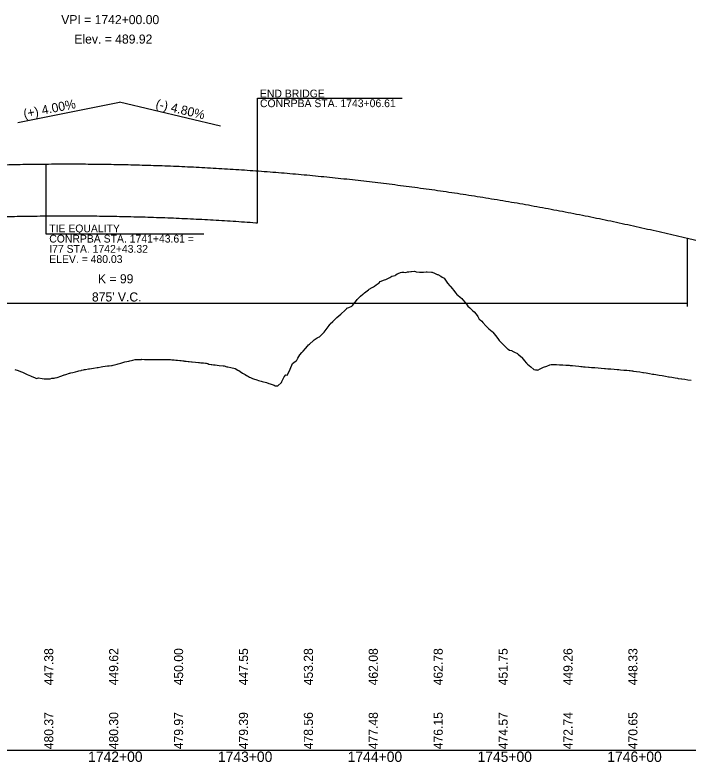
# Model space of a CAD drawing. Extents: x 2017200 to 2047700, y 854850 to 893350.
# Drawn here: x 2022119 to 2022638, y 874091 to 874667 of the extents above; entities that cross this region are included whole.
import ezdxf

# ---------------------------------------------------------------- set-up
doc = ezdxf.new("R2010")
doc.units = 0
for name, color, linetype in [('RD_DDB_GradeTX', 7, 'Continuous'), ('RD_DDB_Profile_EX', 7, 'Continuous'), ('RD_DDB_Profile_Lbl', 7, 'Continuous'), ('RD_DDB_Profile_PR', 7, 'Continuous'), ('RD_DDB_StaTX', 7, 'Continuous'), ('RD_DDB_StripGrade', 7, 'Continuous'), ('RD_DDB_VCLbl', 7, 'Continuous'), ('RD_GPK_Profile_Cell', 7, 'Continuous'), ('RD_PD_Bridge', 7, 'Continuous')]:
    doc.layers.add(name, color=color, linetype=linetype)

msp = doc.modelspace()

# ---------------------------------------------------------------- linework, layer by layer
at = {"layer": 'RD_DDB_GradeTX'}
for p in [(2022121.55, 874583.91), (2022277.79, 874580.93)]:
    msp.add_line(p, (2022200, 874599.6), dxfattribs=at)
at = {"layer": 'RD_DDB_Profile_EX'}
msp.add_lwpolyline([(2022119.33, 874393.34), (2022121.82, 874392.73), (2022122.35, 874392.5), (2022124.57, 874391.55), (2022125.38, 874391.29), (2022126.82, 874390.58), (2022128.41, 874389.89), (2022128.94, 874389.65), (2022130.12, 874388.99), (2022131.43, 874388.47), (2022132.52, 874388.04), (2022134.46, 874387.18), (2022135.63, 874386.67), (2022136.1, 874386.43), (2022137.66, 874386.99), (2022140.51, 874386.48), (2022141.88, 874386.23), (2022142.56, 874386.2), (2022143.5, 874386.17), (2022145.73, 874386.14), (2022146.56, 874386.37), (2022147.87, 874386.73), (2022149.59, 874386.85), (2022150.49, 874386.91), (2022151.92, 874387.4), (2022152.62, 874387.62), (2022154.11, 874388.07), (2022155.64, 874388.63), (2022157.28, 874389.22), (2022157.74, 874389.4), (2022158.7, 874389.7), (2022161.37, 874390.55), (2022161.7, 874390.64), (2022162.6, 874390.87), (2022164.03, 874391.23), (2022165.01, 874391.5), (2022166.18, 874391.76), (2022167.88, 874392.21), (2022168.66, 874392.4), (2022170.43, 874392.79), (2022170.78, 874392.86), (2022172.32, 874393.19), (2022173.13, 874393.36), (2022173.8, 874393.5), (2022175.98, 874393.95), (2022176.83, 874394.06), (2022178.34, 874394.25), (2022179.85, 874394.47), (2022182.88, 874394.94), (2022183.52, 874395.05), (2022185.91, 874395.45), (2022187.03, 874395.64), (2022188.93, 874395.92), (2022190.73, 874396.17), (2022191.96, 874396.33), (2022193.79, 874396.56), (2022194.43, 874396.64), (2022194.99, 874396.76), (2022196.18, 874397.03), (2022198.15, 874397.5), (2022198.87, 874397.73), (2022201.04, 874398.4), (2022201.88, 874398.65), (2022204.07, 874399.24), (2022205.61, 874399.68), (2022207.09, 874399.99), (2022208.01, 874400.18), (2022209.15, 874400.38), (2022210.38, 874400.69), (2022212.02, 874401.05), (2022213.14, 874401.1), (2022216.17, 874401.25), (2022216.95, 874401.27), (2022217.31, 874401.29), (2022219.21, 874401.27), (2022221.26, 874401.26), (2022221.73, 874401.25), (2022222.22, 874401.25), (2022223.51, 874401.23), (2022224.26, 874401.21), (2022225.25, 874401.21), (2022225.76, 874401.2), (2022226.77, 874401.21), (2022228.28, 874401.21), (2022229.28, 874401.19), (2022230.25, 874401.18), (2022231.3, 874401.17), (2022231.78, 874401.17), (2022232.49, 874401.16), (2022234.33, 874401.15), (2022234.73, 874401.15), (2022236.96, 874401.15), (2022237.36, 874401.15), (2022238.62, 874401.13), (2022239.34, 874401.05), (2022240.38, 874400.95), (2022241.66, 874400.82), (2022242.03, 874400.78), (2022243.41, 874400.65), (2022244.05, 874400.59), (2022244.71, 874400.52), (2022246.44, 874400.36), (2022247.39, 874400.26), (2022248.83, 874400.09), (2022249.46, 874400.03), (2022250.06, 874399.98), (2022251.22, 874399.89), (2022252.76, 874399.73), (2022253.62, 874399.65), (2022255.51, 874399.45), (2022255.99, 874399.4), (2022258.54, 874399.14), (2022260.84, 874398.93), (2022261.57, 874398.84), (2022262.75, 874398.7), (2022263.47, 874398.62), (2022264.76, 874398.48), (2022266.22, 874398.29), (2022266.74, 874398.23), (2022267.62, 874398.12), (2022268.15, 874398.05), (2022268.79, 874397.57), (2022270.65, 874397.34), (2022271.06, 874397.28), (2022272.51, 874397.08), (2022273.67, 874396.92), (2022276.7, 874396.58), (2022279.73, 874396.24), (2022280.56, 874396.14), (2022281.45, 874395.93), (2022282.01, 874395.74), (2022282.75, 874395.58), (2022283.41, 874395.44), (2022285.78, 874394.95), (2022288.97, 874394.29), (2022291.15, 874393.04), (2022291.83, 874392.62), (2022292.94, 874391.95), (2022294.86, 874390.73), (2022295.72, 874390.19), (2022296.92, 874389.46), (2022297.88, 874388.91), (2022298.63, 874388.48), (2022300.24, 874387.59), (2022300.91, 874387.21), (2022302.38, 874386.38), (2022303.94, 874386.01), (2022304.92, 874385.77), (2022305.88, 874385.44), (2022306.96, 874385.08), (2022309.13, 874384.36), (2022309.99, 874384.16), (2022313.12, 874383.42), (2022314.96, 874382.75), (2022316.04, 874382.35), (2022317.65, 874381.76), (2022318.26, 874381.55), (2022319.07, 874381.26), (2022319.92, 874380.93), (2022321.31, 874380.87), (2022321.88, 874380.84), (2022324.8, 874383.5), (2022325.12, 874384.16), (2022326.88, 874387.8), (2022328.15, 874389.25), (2022329.22, 874389.1), (2022331.17, 874392.81), (2022331.58, 874393.57), (2022333.32, 874398.15), (2022334.2, 874398.78), (2022335.97, 874400.04), (2022336.72, 874400.63), (2022337.43, 874402.12), (2022338.85, 874404.71), (2022340.35, 874406.53), (2022341.56, 874407.51), (2022343.28, 874409.66), (2022344.71, 874411.44), (2022345.69, 874412.51), (2022346.31, 874413.03), (2022349.33, 874415.69), (2022349.85, 874416.32), (2022352.36, 874417.84), (2022353.38, 874418.45), (2022354.02, 874418.56), (2022355.38, 874419.97), (2022357.69, 874422.31), (2022358.41, 874423.27), (2022361.44, 874427.39), (2022361.98, 874428.13), (2022362.39, 874428.73), (2022364.46, 874430.45), (2022366.26, 874432.33), (2022366.61, 874432.72), (2022367.49, 874433.5), (2022370.52, 874436.16), (2022370.83, 874436.32), (2022373.54, 874439.04), (2022374.77, 874440.27), (2022375.08, 874440.6), (2022376.57, 874441.23), (2022379, 874442.24), (2022379.6, 874442.79), (2022382.62, 874446.71), (2022383.21, 874447.47), (2022383.61, 874447.91), (2022385.65, 874449.84), (2022387.41, 874451.5), (2022387.9, 874451.84), (2022388.68, 874452.47), (2022391.7, 874454.9), (2022392.21, 874455.3), (2022394.73, 874456.61), (2022395.76, 874457.14), (2022396.53, 874457.59), (2022397.75, 874458.57), (2022399.92, 874460.3), (2022400.88, 874461.32), (2022404.06, 874462.53), (2022405.24, 874462.71), (2022406.83, 874463.6), (2022408.18, 874464.35), (2022409.86, 874465.34), (2022412.3, 874465.97), (2022412.89, 874466.38), (2022414.01, 874467.16), (2022415.91, 874467.95), (2022416.39, 874468.15), (2022417.37, 874468.47), (2022418.42, 874468.41), (2022418.94, 874468.37), (2022420.48, 874468.27), (2022421.97, 874468.62), (2022422.85, 874468.82), (2022424.55, 874469.07), (2022424.99, 874469.08), (2022427.3, 874469.14), (2022428.02, 874468.97), (2022428.61, 874468.84), (2022431.04, 874468.57), (2022431.77, 874468.49), (2022432.65, 874468.41), (2022434.07, 874468.55), (2022436.26, 874468.76), (2022436.69, 874468.72), (2022437.1, 874468.7), (2022440.24, 874468.58), (2022440.77, 874468.53), (2022442.6, 874467.67), (2022444.71, 874466.67), (2022445.3, 874466.54), (2022447.54, 874465.33), (2022448.69, 874464.71), (2022450.01, 874463.87), (2022452.66, 874460.06), (2022454.46, 874458.02), (2022454.96, 874457.46), (2022456.61, 874455.56), (2022457.43, 874454.51), (2022459.09, 874452.38), (2022459.9, 874451.2), (2022460.54, 874450.76), (2022462.37, 874449.26), (2022463.76, 874448.14), (2022464.46, 874447.24), (2022464.84, 874446.77), (2022467.32, 874443.73), (2022467.9, 874443.03), (2022468.45, 874442.36), (2022469.79, 874441.08), (2022472.26, 874438.72), (2022473.19, 874437.91), (2022474.73, 874436), (2022476.1, 874434.31), (2022477.2, 874432.23), (2022477.96, 874431.59), (2022479.07, 874430.71), (2022479.96, 874429.75), (2022482.15, 874427.22), (2022482.76, 874426.52), (2022483.79, 874425.53), (2022484.62, 874424.8), (2022487.09, 874422.64), (2022487.62, 874422.18), (2022489.56, 874419.66), (2022491.41, 874417.28), (2022492.04, 874416.44), (2022492.49, 874415.83), (2022494.51, 874413.68), (2022495.2, 874412.94), (2022496.98, 874411.28), (2022497.42, 874410.88), (2022498.98, 874409.4), (2022499.45, 874409.09), (2022500.45, 874408.45), (2022501.92, 874408.01), (2022502.38, 874407.88), (2022502.82, 874407.67), (2022503.82, 874407.12), (2022504.4, 874406.81), (2022506.49, 874405.68), (2022506.87, 874405.38), (2022507.39, 874404.97), (2022509.34, 874403.18), (2022509.73, 874402.82), (2022511.22, 874401.26), (2022511.81, 874400.5), (2022513.55, 874398.29), (2022514.28, 874397.64), (2022516.76, 874395.49), (2022519.16, 874393.42), (2022520.37, 874393.27), (2022521.7, 874393.1), (2022522.24, 874393.03), (2022524.17, 874393.94), (2022526.71, 874395.11), (2022529.12, 874396.08), (2022531.59, 874397.06), (2022532.53, 874397.42), (2022534.06, 874397.34), (2022536.53, 874397.2), (2022539, 874397.07), (2022539.55, 874397.03), (2022541.48, 874396.94), (2022543.95, 874396.82), (2022545.62, 874396.74), (2022546.42, 874396.66), (2022547.06, 874396.59), (2022548.89, 874396.41), (2022551.37, 874396.17), (2022553.84, 874395.92), (2022555.3, 874395.78), (2022556.31, 874395.71), (2022557.52, 874395.62), (2022558.78, 874395.5), (2022561.25, 874395.24), (2022561.85, 874395.18), (2022563.73, 874395.06), (2022566.2, 874394.89), (2022568.67, 874394.65), (2022571.14, 874394.42), (2022573.61, 874394.26), (2022574.47, 874394.21), (2022576.09, 874394.06), (2022577.53, 874393.92), (2022578.56, 874393.84), (2022581.03, 874393.65), (2022583.5, 874393.45), (2022584.76, 874393.35), (2022586.06, 874393.23), (2022588.45, 874393.05), (2022590.92, 874392.85), (2022592.75, 874392.71), (2022593.39, 874392.62), (2022594.66, 874392.43), (2022595.09, 874392.37), (2022595.86, 874392.26), (2022598.33, 874391.89), (2022600.81, 874391.53), (2022603.28, 874391.17), (2022603.6, 874391.13), (2022605.75, 874390.76), (2022608.23, 874390.38), (2022610.69, 874389.96), (2022611.53, 874389.81), (2022613.17, 874389.54), (2022615.64, 874389.14), (2022618.16, 874388.72), (2022620.58, 874388.3), (2022623.05, 874387.86), (2022623.36, 874387.81), (2022625.53, 874387.45), (2022628.08, 874387.03), (2022629.89, 874386.71), (2022630.47, 874386.62), (2022632.94, 874386.21), (2022633.28, 874386.15), (2022635.41, 874385.9), (2022637.89, 874385.6), (2022640.36, 874385.3)], dxfattribs=at)
at = {"layer": 'RD_DDB_Profile_Lbl'}
for points in [[(2022306.31, 874546.51), (2022306.31, 874602.58), (2022417.63, 874602.58)], [(2022264.94, 874497.62), (2022143.61, 874497.62), (2022143.61, 874551.8)]]:
    msp.add_lwpolyline(points, dxfattribs=at)
at = {"layer": 'RD_DDB_Profile_PR'}
msp.add_line((2022637.5, 874494.6), (2022900, 874431.6), dxfattribs=at)
msp.add_spline([(2021762.5, 874512.1), (2021780, 874515.52), (2021797.5, 874518.79), (2021815, 874521.91), (2021832.5, 874524.87), (2021850, 874527.67), (2021867.5, 874530.33), (2021885, 874532.83), (2021902.5, 874535.17), (2021920, 874537.36), (2021937.5, 874539.4), (2021955, 874541.28), (2021972.5, 874543.01), (2021990, 874544.59), (2022007.5, 874546.01), (2022025, 874547.27), (2022042.5, 874548.39), (2022060, 874549.35), (2022077.5, 874550.15), (2022095, 874550.8), (2022112.5, 874551.3), (2022130, 874551.64), (2022147.5, 874551.83), (2022165, 874551.87), (2022182.5, 874551.75), (2022200, 874551.48), (2022217.5, 874551.05), (2022235, 874550.47), (2022252.5, 874549.73), (2022270, 874548.84), (2022287.5, 874547.8), (2022305, 874546.6), (2022322.5, 874545.25), (2022340, 874543.75), (2022357.5, 874542.09), (2022375, 874540.28), (2022392.5, 874538.31), (2022410, 874536.19), (2022427.5, 874533.91), (2022445, 874531.48), (2022462.5, 874528.9), (2022480, 874526.16), (2022497.5, 874523.27), (2022515, 874520.23), (2022532.5, 874517.03), (2022550, 874513.68), (2022567.5, 874510.17), (2022585, 874506.51), (2022602.5, 874502.69), (2022620, 874498.72), (2022637.5, 874494.6)], degree=3, dxfattribs=at)
at = {"layer": 'RD_DDB_VCLbl'}
for p, q in [((2022637.5, 874442.1), (2022637.5, 874494.6)), ((2021762.5, 874444.6), (2022637.5, 874444.6))]:
    msp.add_line(p, q, dxfattribs=at)
at = {"layer": 'RD_GPK_Profile_Cell'}
msp.add_line((2020500, 874100), (2023600, 874100), dxfattribs=at)
at = {"layer": 'RD_PD_Bridge'}
msp.add_line((2022306.31, 874506.51), (2022306.31, 874546.51), dxfattribs=at)
msp.add_spline([(2021988.61, 874504.47), (2021990, 874504.59), (2022007.5, 874506.01), (2022025, 874507.27), (2022042.5, 874508.39), (2022060, 874509.35), (2022077.5, 874510.15), (2022095, 874510.8), (2022112.5, 874511.3), (2022130, 874511.64), (2022147.5, 874511.83), (2022165, 874511.87), (2022182.5, 874511.75), (2022200, 874511.48), (2022217.5, 874511.05), (2022235, 874510.47), (2022252.5, 874509.73), (2022270, 874508.84), (2022287.5, 874507.8), (2022305, 874506.6), (2022306.31, 874506.51)], degree=3, dxfattribs=at)

# ---------------------------------------------------------------- texts
at = {"layer": 'RD_DDB_GradeTX'}
for s, rotation, p in [('(+) 4.00%', 11.30994, (2022126.72, 874586.98)), ('(-) 4.80%', 346.50428, (2022227.38, 874595.08))]:
    msp.add_text(s, height=7, rotation=rotation, dxfattribs=at).set_placement(p)
at = {"layer": 'RD_DDB_Profile_Lbl'}
for s, height, p in [('VPI = 1742+00.00', 7, (2022155.1, 874659.6)), ('VPI = 1742+00.00', 7, (2022155.1, 874659.6)), ('Elev. = 489.92', 7, (2022165.19, 874644.6)), ('Elev. = 489.92', 7, (2022165.19, 874644.6)), ('END BRIDGE', 6, (2022308.21, 874603.14)), ('CONRPBA STA. 1743+06.61', 6, (2022308.21, 874595.64)), ('TIE EQUALITY', 6, (2022145.87, 874499.15)), ('CONRPBA STA. 1741+43.61 =', 6, (2022145.87, 874491.28)), ('I77 STA. 1742+43.32', 6, (2022145.87, 874483.41)), ('ELEV. = 480.03', 6, (2022145.87, 874475.54))]:
    msp.add_text(s, height=height, dxfattribs=at).set_placement(p)
at = {"layer": 'RD_DDB_StaTX'}
for s, p in [('1742+00', (2022175.8, 874091)), ('1743+00', (2022275.8, 874091)), ('1744+00', (2022375.8, 874091)), ('1745+00', (2022475.8, 874091)), ('1746+00', (2022575.8, 874091))]:
    msp.add_text(s, height=8, dxfattribs=at).set_placement(p)
at = {"layer": 'RD_DDB_StripGrade'}
for s, p in [('447.38', (2022149, 874150)), ('449.62', (2022199, 874150)), ('450.00', (2022249, 874150)), ('447.55', (2022299, 874150)), ('453.28', (2022349, 874150)), ('462.08', (2022399, 874150)), ('462.78', (2022449, 874150)), ('451.75', (2022499, 874150)), ('449.26', (2022549, 874150)), ('448.33', (2022599, 874150)), ('480.37', (2022149, 874100.75)), ('480.30', (2022199, 874100.75)), ('479.97', (2022249, 874100.75)), ('479.39', (2022299, 874100.75)), ('478.56', (2022349, 874100.75)), ('477.48', (2022399, 874100.75)), ('476.15', (2022449, 874100.75)), ('474.57', (2022499, 874100.75)), ('472.74', (2022549, 874100.75)), ('470.65', (2022599, 874100.75))]:
    msp.add_text(s, height=7, rotation=90, dxfattribs=at).set_placement(p)
at = {"layer": 'RD_DDB_VCLbl'}
for s, p in [('K = 99', (2022183.38, 874459.85)), ("875' V.C.", (2022178.75, 874445.85))]:
    msp.add_text(s, height=7, dxfattribs=at).set_placement(p)

doc.saveas('drawing.dxf')
